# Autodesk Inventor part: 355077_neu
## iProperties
Created: 2006-10
Part Number: 355077_neu
Material: 1.0718.07
Description: Rilllenbolzen
Document SubType Name: Modeling
Designer: OSchmidt
Density: 7.84 g/cm^3
Mass: 33.2556 g
Surface Area: 16.4545 cm^2
Volume: 4.24179 cm^3
Abmessung: Rd. 12
HalbzeugNorm: DIN 671
Zweck: 266450
Author: Natti_01
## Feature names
1. Extrusion2
2. Fase1 [Chamfer]
3. Extrusion3
4. Spiegeln1 [Mirror]
